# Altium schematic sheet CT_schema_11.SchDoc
size 387 x 278 mm
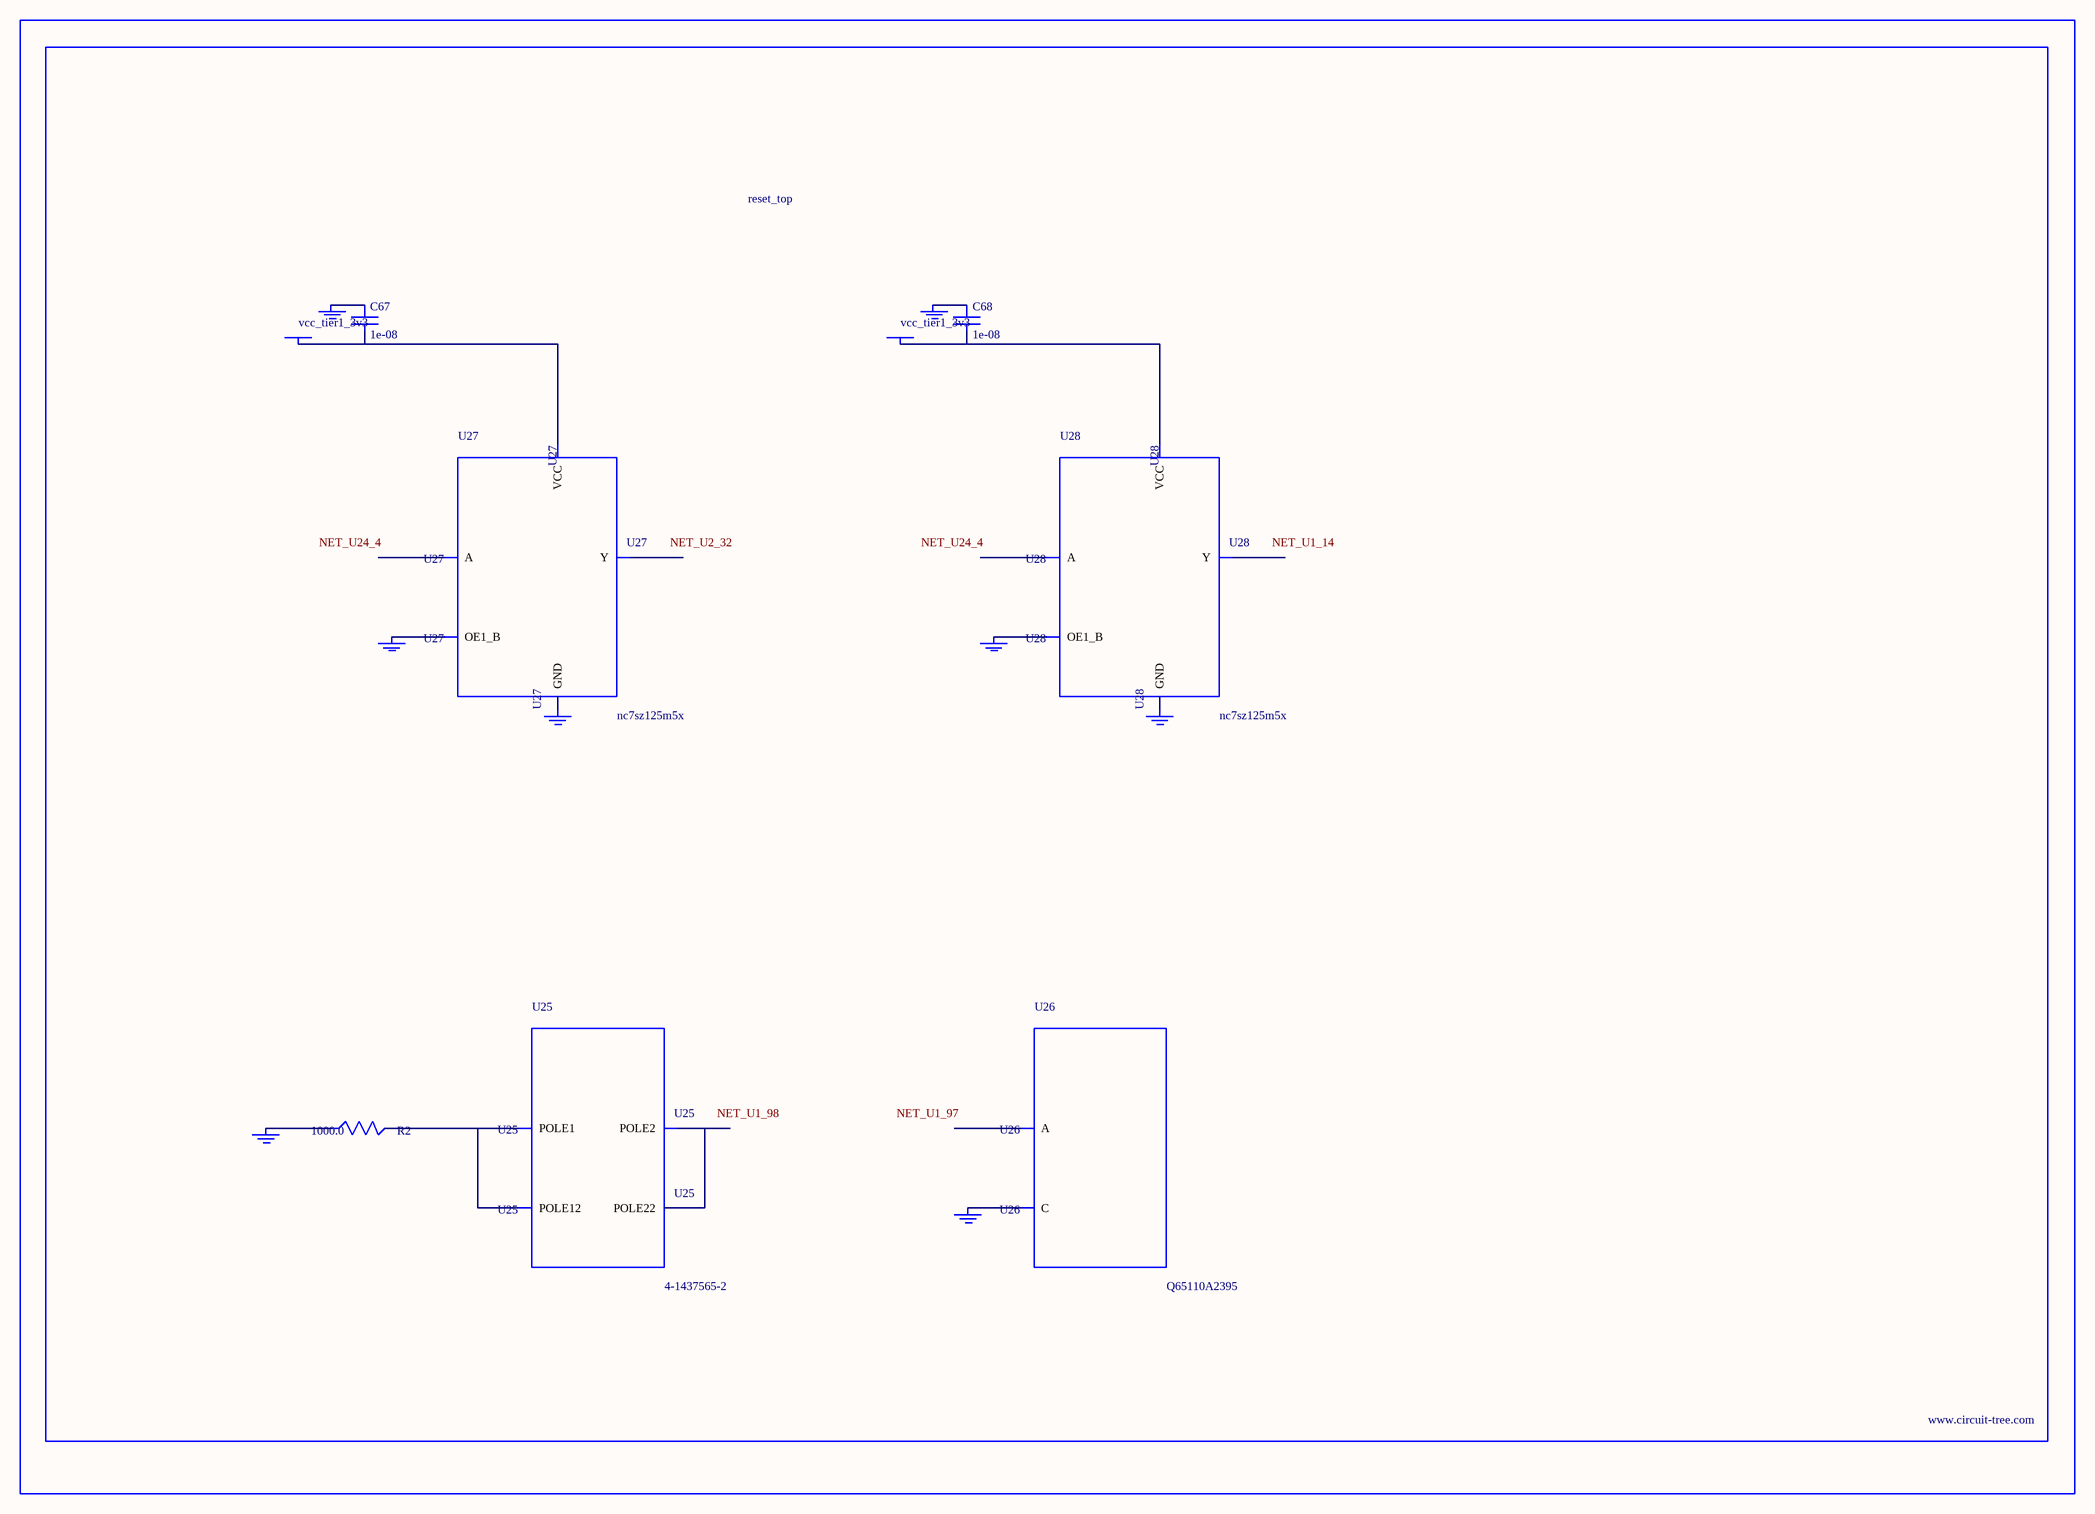
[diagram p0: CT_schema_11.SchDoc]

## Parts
BORDER10  (no value)
C67  1e-08  [C0402]
C68  1e-08  [C0402]
GND_INSTANCE_10_0  (no value)
GND_INSTANCE_10_1  (no value)
GND_INSTANCE_10_2  (no value)
GND_INSTANCE_10_3  (no value)
GND_INSTANCE_10_4  (no value)
GND_INSTANCE_10_5  (no value)
GND_INSTANCE_10_6  (no value)
GND_INSTANCE_10_7  (no value)
POWER_INSTANCE_10_0  vcc_tier1_3v3
POWER_INSTANCE_10_1  vcc_tier1_3v3
R2  1000.0  [R0603]
U25  4-1437565-2  [SW_4-1437565-2]
U26  Q65110A2395  [LGM67K-G1J2-24-Z]
U27  nc7sz125m5x  [NC7SZ125M5X]
U28  nc7sz125m5x  [NC7SZ125M5X]

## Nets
NetC67_1: C67.1 GND_INSTANCE_10_2.0(GND)
NetC67_2: C67.2 POWER_INSTANCE_10_0.0(PWR) U27.5(VCC)
NetC68_1: C68.1 GND_INSTANCE_10_5.0(GND)
NetC68_2: C68.2 POWER_INSTANCE_10_1.0(PWR) U28.5(VCC)
NetGND_INSTANCE_10_0_0: GND_INSTANCE_10_0.0(GND) R2.1
NetGND_INSTANCE_10_1_0: GND_INSTANCE_10_1.0(GND) U26.C
NetGND_INSTANCE_10_3_0: GND_INSTANCE_10_3.0(GND) U27.1(OE1_B)
NetGND_INSTANCE_10_4_0: GND_INSTANCE_10_4.0(GND) U27.3(GND)
NetGND_INSTANCE_10_6_0: GND_INSTANCE_10_6.0(GND) U28.1(OE1_B)
NetGND_INSTANCE_10_7_0: GND_INSTANCE_10_7.0(GND) U28.3(GND)
NetR2_2: R2.2 U25.1(POLE1) U25.2(POLE12)
NetU25_3: U25.3(POLE2) U25.4(POLE22)

Not connected (* = marked no-connect by the designer): U26 A; U27 2(A) 4(Y); U28 2(A) 4(Y)

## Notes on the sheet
- Labels drawn without touching a wire or pin: NET_U1_14, NET_U1_97, NET_U1_98, NET_U2_32, NET_U24_4

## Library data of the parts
BORDER10 = BORDER_PAGE10
C67 C68 = C0402C103K3RAC
GND_INSTANCE_10_0-GND_INSTANCE_10_7 = GND
POWER_INSTANCE_10_0 POWER_INSTANCE_10_1 = PWR
R2 = RC0603JR-071KL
